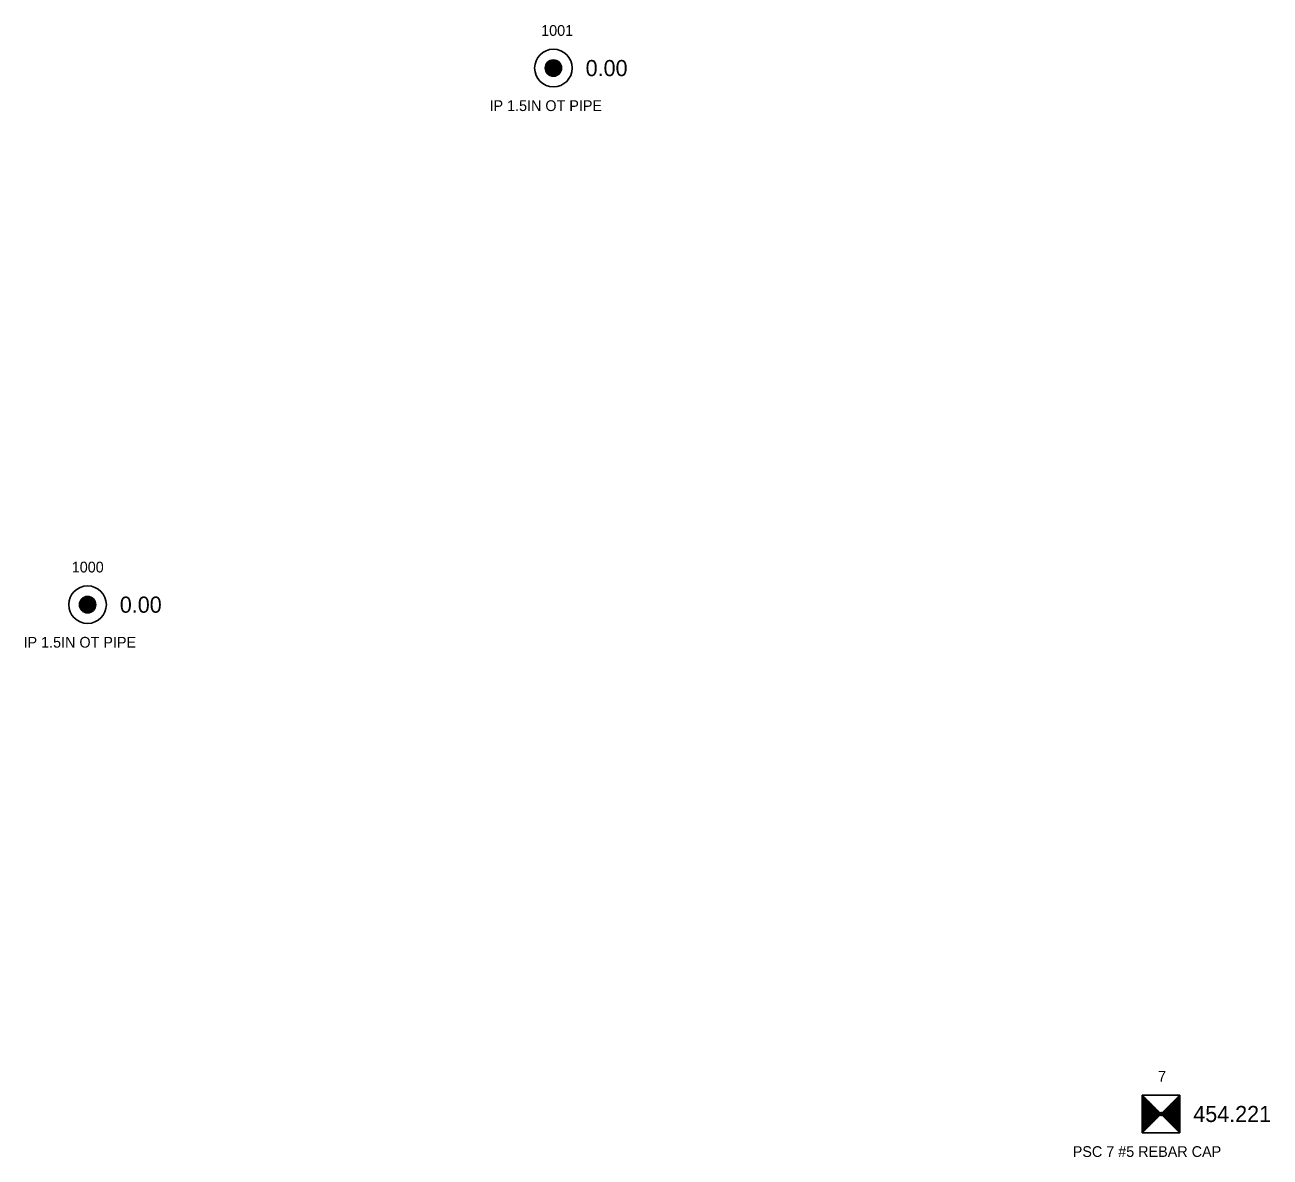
# Model space of a CAD drawing. Extents: x 1611865 to 1617004, y 775289 to 778546.
# Drawn here: x 1615669.9 to 1615785.8, y 776629.9 to 776735.3 of the extents above; entities that cross this region are included whole.
import ezdxf

# ---------------------------------------------------------------- set-up
doc = ezdxf.new("R2010")
doc.units = 0
for name, color, linetype in [('RD_EX_DV_Prop_txCode', 7, 'Continuous'), ('RD_EX_DV_PropPin', 7, 'Continuous'), ('RD_EX_TX_DV_Prop_ELEV', 7, 'Continuous'), ('RD_HC_Survey', 7, 'Continuous'), ('RD_HC_Survey_ELEV', 7, 'Continuous'), ('RD_HC_txCode', 7, 'Continuous'), ('RD_SMD_Locator', 7, 'Continuous')]:
    doc.layers.add(name, color=color, linetype=linetype)

msp = doc.modelspace()

# ---------------------------------------------------------------- linework, layer by layer
at = {"layer": 'RD_EX_DV_PropPin'}
for p, q in [((1615718.37, 776731.1), (1615718.37, 776731.49)), ((1615718.4, 776730.99), (1615718.4, 776731.59)), ((1615718.44, 776730.92), (1615718.44, 776731.66)), ((1615718.47, 776730.87), (1615718.47, 776731.72)), ((1615718.51, 776730.82), (1615718.51, 776731.77)), ((1615718.54, 776730.78), (1615718.54, 776731.81)), ((1615718.58, 776730.74), (1615718.58, 776731.84)), ((1615718.61, 776730.71), (1615718.61, 776731.87)), ((1615718.65, 776730.68), (1615718.65, 776731.9)), ((1615718.68, 776730.66), (1615718.68, 776731.93)), ((1615718.72, 776730.64), (1615718.72, 776731.95)), ((1615718.75, 776730.62), (1615718.75, 776731.97)), ((1615718.79, 776730.6), (1615718.79, 776731.99)), ((1615718.82, 776730.58), (1615718.82, 776732)), ((1615718.86, 776730.57), (1615718.86, 776732.01)), ((1615718.89, 776730.56), (1615718.89, 776732.02)), ((1615718.93, 776730.55), (1615718.93, 776732.03)), ((1615718.96, 776730.54), (1615718.96, 776732.04)), ((1615719, 776730.54), (1615719, 776732.05)), ((1615719.03, 776730.53), (1615719.03, 776732.05)), ((1615719.07, 776730.53), (1615719.07, 776732.05)), ((1615719.1, 776730.53), (1615719.1, 776732.05)), ((1615719.14, 776730.53), (1615719.14, 776732.05)), ((1615719.17, 776730.53), (1615719.17, 776732.05)), ((1615719.21, 776730.54), (1615719.21, 776732.05)), ((1615719.24, 776730.54), (1615719.24, 776732.04)), ((1615719.28, 776730.55), (1615719.28, 776732.03)), ((1615719.31, 776730.56), (1615719.31, 776732.02)), ((1615719.35, 776730.57), (1615719.35, 776732.01)), ((1615719.38, 776730.58), (1615719.38, 776732)), ((1615719.42, 776730.6), (1615719.42, 776731.99)), ((1615719.45, 776730.62), (1615719.45, 776731.97)), ((1615719.49, 776730.64), (1615719.49, 776731.95)), ((1615719.52, 776730.66), (1615719.52, 776731.93)), ((1615719.56, 776730.68), (1615719.56, 776731.9)), ((1615719.59, 776730.71), (1615719.59, 776731.87)), ((1615719.63, 776730.74), (1615719.63, 776731.84)), ((1615719.66, 776730.78), (1615719.66, 776731.81)), ((1615719.7, 776730.82), (1615719.7, 776731.77)), ((1615719.73, 776730.87), (1615719.73, 776731.72)), ((1615719.77, 776730.92), (1615719.77, 776731.66)), ((1615719.8, 776730.99), (1615719.8, 776731.59)), ((1615719.84, 776731.1), (1615719.84, 776731.49)), ((1615674.98, 776681.15), (1615674.98, 776681.54)), ((1615675.02, 776681.04), (1615675.02, 776681.64)), ((1615675.05, 776680.97), (1615675.05, 776681.71)), ((1615675.09, 776680.91), (1615675.09, 776681.77)), ((1615675.12, 776680.87), (1615675.12, 776681.82)), ((1615675.16, 776680.83), (1615675.16, 776681.86)), ((1615675.19, 776680.79), (1615675.19, 776681.89)), ((1615675.23, 776680.76), (1615675.23, 776681.92)), ((1615675.26, 776680.73), (1615675.26, 776681.95)), ((1615675.3, 776680.71), (1615675.3, 776681.98)), ((1615675.33, 776680.69), (1615675.33, 776682)), ((1615675.37, 776680.67), (1615675.37, 776682.02)), ((1615675.4, 776680.65), (1615675.4, 776682.03)), ((1615675.44, 776680.63), (1615675.44, 776682.05)), ((1615675.47, 776680.62), (1615675.47, 776682.06)), ((1615675.51, 776680.61), (1615675.51, 776682.07)), ((1615675.54, 776680.6), (1615675.54, 776682.08)), ((1615675.58, 776680.59), (1615675.58, 776682.09)), ((1615675.61, 776680.59), (1615675.61, 776682.1)), ((1615675.65, 776680.58), (1615675.65, 776682.1)), ((1615675.68, 776680.58), (1615675.68, 776682.1)), ((1615675.72, 776680.58), (1615675.72, 776682.1)), ((1615675.75, 776680.58), (1615675.75, 776682.1)), ((1615675.79, 776680.58), (1615675.79, 776682.1)), ((1615675.82, 776680.59), (1615675.82, 776682.1)), ((1615675.86, 776680.59), (1615675.86, 776682.09)), ((1615675.89, 776680.6), (1615675.89, 776682.08)), ((1615675.93, 776680.61), (1615675.93, 776682.07)), ((1615675.96, 776680.62), (1615675.96, 776682.06)), ((1615676, 776680.63), (1615676, 776682.05)), ((1615676.03, 776680.65), (1615676.03, 776682.03)), ((1615676.07, 776680.67), (1615676.07, 776682.02)), ((1615676.1, 776680.69), (1615676.1, 776682)), ((1615676.14, 776680.71), (1615676.14, 776681.98)), ((1615676.17, 776680.73), (1615676.17, 776681.95)), ((1615676.21, 776680.76), (1615676.21, 776681.92)), ((1615676.24, 776680.79), (1615676.24, 776681.89)), ((1615676.28, 776680.83), (1615676.28, 776681.86)), ((1615676.31, 776680.87), (1615676.31, 776681.82)), ((1615676.35, 776680.91), (1615676.35, 776681.77)), ((1615676.38, 776680.97), (1615676.38, 776681.71)), ((1615676.42, 776681.04), (1615676.42, 776681.64)), ((1615676.45, 776681.15), (1615676.45, 776681.54))]:
    msp.add_line(p, q, dxfattribs=at)
for centre, radius in [((1615719.1, 776731.29), 1.75), ((1615719.1, 776731.29), 0.761), ((1615675.72, 776681.34), 1.75), ((1615675.72, 776681.34), 0.761)]:
    msp.add_circle(centre, radius, dxfattribs=at)
at = {"layer": 'RD_HC_Survey'}
for p, q in [((1615773.93, 776635.68), (1615777.43, 776632.18)), ((1615777.43, 776635.68), (1615773.93, 776632.18)), ((1615773.96, 776635.66), (1615773.96, 776632.21)), ((1615773.98, 776635.63), (1615773.98, 776632.23)), ((1615774.01, 776635.61), (1615774.01, 776632.25)), ((1615774.03, 776635.58), (1615774.03, 776632.28)), ((1615774.06, 776635.56), (1615774.06, 776632.3)), ((1615774.08, 776635.53), (1615774.08, 776632.33)), ((1615774.11, 776635.51), (1615774.11, 776632.35)), ((1615774.13, 776635.48), (1615774.13, 776632.38)), ((1615774.16, 776635.46), (1615774.16, 776632.4)), ((1615774.18, 776635.43), (1615774.18, 776632.43)), ((1615774.21, 776635.41), (1615774.21, 776632.45)), ((1615774.23, 776635.38), (1615774.23, 776632.48)), ((1615774.26, 776635.36), (1615774.26, 776632.5)), ((1615774.28, 776635.33), (1615774.28, 776632.53)), ((1615774.31, 776635.31), (1615774.31, 776632.55)), ((1615774.33, 776635.28), (1615774.33, 776632.58)), ((1615774.35, 776635.26), (1615774.35, 776632.6)), ((1615774.38, 776635.23), (1615774.38, 776632.63)), ((1615774.4, 776635.21), (1615774.4, 776632.65)), ((1615774.43, 776635.19), (1615774.43, 776632.68)), ((1615774.45, 776635.16), (1615774.45, 776632.7)), ((1615774.48, 776635.14), (1615774.48, 776632.72)), ((1615774.5, 776635.11), (1615774.5, 776632.75)), ((1615774.53, 776635.09), (1615774.53, 776632.77)), ((1615774.55, 776635.06), (1615774.55, 776632.8)), ((1615774.58, 776635.04), (1615774.58, 776632.82)), ((1615774.6, 776635.01), (1615774.6, 776632.85)), ((1615774.63, 776634.99), (1615774.63, 776632.87)), ((1615774.65, 776634.96), (1615774.65, 776632.9)), ((1615774.68, 776634.94), (1615774.68, 776632.92)), ((1615774.7, 776634.91), (1615774.7, 776632.95)), ((1615774.73, 776634.89), (1615774.73, 776632.97)), ((1615774.75, 776634.86), (1615774.75, 776633)), ((1615774.78, 776634.84), (1615774.78, 776633.02)), ((1615774.8, 776634.81), (1615774.8, 776633.05)), ((1615774.83, 776634.79), (1615774.83, 776633.07)), ((1615774.85, 776634.76), (1615774.85, 776633.1)), ((1615774.87, 776634.74), (1615774.87, 776633.12)), ((1615774.9, 776634.72), (1615774.9, 776633.15)), ((1615774.92, 776634.69), (1615774.92, 776633.17)), ((1615776.44, 776634.69), (1615776.44, 776633.17)), ((1615776.47, 776634.72), (1615776.47, 776633.15)), ((1615776.49, 776634.74), (1615776.49, 776633.12)), ((1615776.52, 776634.76), (1615776.52, 776633.1)), ((1615776.54, 776634.79), (1615776.54, 776633.07)), ((1615776.57, 776634.81), (1615776.57, 776633.05)), ((1615776.59, 776634.84), (1615776.59, 776633.02)), ((1615776.62, 776634.86), (1615776.62, 776633)), ((1615776.64, 776634.89), (1615776.64, 776632.97)), ((1615776.67, 776634.91), (1615776.67, 776632.95)), ((1615776.69, 776634.94), (1615776.69, 776632.92)), ((1615776.72, 776634.96), (1615776.72, 776632.9)), ((1615776.74, 776634.99), (1615776.74, 776632.87)), ((1615776.77, 776635.01), (1615776.77, 776632.85)), ((1615776.79, 776635.04), (1615776.79, 776632.82)), ((1615776.82, 776635.06), (1615776.82, 776632.8)), ((1615776.84, 776635.09), (1615776.84, 776632.77)), ((1615776.86, 776635.11), (1615776.86, 776632.75)), ((1615776.89, 776635.14), (1615776.89, 776632.72)), ((1615776.91, 776635.16), (1615776.91, 776632.7)), ((1615776.94, 776635.19), (1615776.94, 776632.68)), ((1615776.96, 776635.21), (1615776.96, 776632.65)), ((1615776.99, 776635.23), (1615776.99, 776632.63)), ((1615777.01, 776635.26), (1615777.01, 776632.6)), ((1615777.04, 776635.28), (1615777.04, 776632.58)), ((1615777.06, 776635.31), (1615777.06, 776632.55)), ((1615777.09, 776635.33), (1615777.09, 776632.53)), ((1615777.11, 776635.36), (1615777.11, 776632.5)), ((1615777.14, 776635.38), (1615777.14, 776632.48)), ((1615777.16, 776635.41), (1615777.16, 776632.45)), ((1615777.19, 776635.43), (1615777.19, 776632.43)), ((1615777.21, 776635.46), (1615777.21, 776632.4)), ((1615777.24, 776635.48), (1615777.24, 776632.38)), ((1615777.26, 776635.51), (1615777.26, 776632.35)), ((1615777.29, 776635.53), (1615777.29, 776632.33)), ((1615777.31, 776635.56), (1615777.31, 776632.3)), ((1615777.34, 776635.58), (1615777.34, 776632.28)), ((1615777.36, 776635.61), (1615777.36, 776632.25)), ((1615777.38, 776635.63), (1615777.38, 776632.23)), ((1615777.41, 776635.66), (1615777.41, 776632.21)), ((1615774.95, 776634.67), (1615774.95, 776633.2)), ((1615774.97, 776634.64), (1615774.97, 776633.22)), ((1615775, 776634.62), (1615775, 776633.24)), ((1615775.02, 776634.59), (1615775.02, 776633.27)), ((1615775.05, 776634.57), (1615775.05, 776633.29)), ((1615775.07, 776634.54), (1615775.07, 776633.32)), ((1615775.1, 776634.52), (1615775.1, 776633.34)), ((1615775.12, 776634.49), (1615775.12, 776633.37)), ((1615775.15, 776634.47), (1615775.15, 776633.39)), ((1615775.17, 776634.44), (1615775.17, 776633.42)), ((1615775.2, 776634.42), (1615775.2, 776633.44)), ((1615775.22, 776634.39), (1615775.22, 776633.47)), ((1615775.25, 776634.37), (1615775.25, 776633.49)), ((1615775.27, 776634.34), (1615775.27, 776633.52)), ((1615775.3, 776634.32), (1615775.3, 776633.54)), ((1615775.32, 776634.29), (1615775.32, 776633.57)), ((1615775.34, 776634.27), (1615775.34, 776633.59)), ((1615775.37, 776634.24), (1615775.37, 776633.62)), ((1615775.39, 776634.22), (1615775.39, 776633.64)), ((1615775.42, 776634.2), (1615775.42, 776633.67)), ((1615775.44, 776634.17), (1615775.44, 776633.69)), ((1615775.47, 776634.15), (1615775.47, 776633.71)), ((1615775.49, 776634.12), (1615775.49, 776633.74)), ((1615775.52, 776634.1), (1615775.52, 776633.76)), ((1615775.54, 776634.07), (1615775.54, 776633.79)), ((1615775.57, 776634.05), (1615775.57, 776633.81)), ((1615775.59, 776634.02), (1615775.59, 776633.84)), ((1615775.62, 776634), (1615775.62, 776633.86)), ((1615775.64, 776633.97), (1615775.64, 776633.89)), ((1615775.67, 776633.95), (1615775.67, 776633.91)), ((1615775.7, 776633.95), (1615775.7, 776633.91)), ((1615775.73, 776633.97), (1615775.73, 776633.89)), ((1615775.75, 776634), (1615775.75, 776633.86)), ((1615775.78, 776634.02), (1615775.78, 776633.84)), ((1615775.8, 776634.05), (1615775.8, 776633.81)), ((1615775.83, 776634.07), (1615775.83, 776633.79)), ((1615775.85, 776634.1), (1615775.85, 776633.76)), ((1615775.87, 776634.12), (1615775.87, 776633.74)), ((1615775.9, 776634.15), (1615775.9, 776633.71)), ((1615775.92, 776634.17), (1615775.92, 776633.69)), ((1615775.95, 776634.2), (1615775.95, 776633.67)), ((1615775.97, 776634.22), (1615775.97, 776633.64)), ((1615776, 776634.24), (1615776, 776633.62)), ((1615776.02, 776634.27), (1615776.02, 776633.59)), ((1615776.05, 776634.29), (1615776.05, 776633.57)), ((1615776.07, 776634.32), (1615776.07, 776633.54)), ((1615776.1, 776634.34), (1615776.1, 776633.52)), ((1615776.12, 776634.37), (1615776.12, 776633.49)), ((1615776.15, 776634.39), (1615776.15, 776633.47)), ((1615776.17, 776634.42), (1615776.17, 776633.44)), ((1615776.2, 776634.44), (1615776.2, 776633.42)), ((1615776.22, 776634.47), (1615776.22, 776633.39)), ((1615776.25, 776634.49), (1615776.25, 776633.37)), ((1615776.27, 776634.52), (1615776.27, 776633.34)), ((1615776.3, 776634.54), (1615776.3, 776633.32)), ((1615776.32, 776634.57), (1615776.32, 776633.29)), ((1615776.35, 776634.59), (1615776.35, 776633.27)), ((1615776.37, 776634.62), (1615776.37, 776633.24)), ((1615776.39, 776634.64), (1615776.39, 776633.22)), ((1615776.42, 776634.67), (1615776.42, 776633.2))]:
    msp.add_line(p, q, dxfattribs=at)
msp.add_lwpolyline([(1615777.43, 776635.68), (1615773.93, 776635.68), (1615773.93, 776632.18), (1615777.43, 776632.18)], close=True, dxfattribs=at)
at = {"layer": 'RD_SMD_Locator'}
for centre in [(1615719.1, 776731.29), (1615675.72, 776681.34), (1615775.68, 776633.93)]:
    msp.add_circle(centre, 0.15, dxfattribs=at)

# ---------------------------------------------------------------- texts
at = {"layer": 'RD_EX_DV_Prop_txCode'}
for s, p in [('1001', (1615717.96, 776734.29)), ('IP 1.5IN OT PIPE', (1615713.15, 776727.29)), ('1000', (1615674.25, 776684.34)), ('IP 1.5IN OT PIPE', (1615669.76, 776677.34))]:
    msp.add_text(s, height=1, dxfattribs=at).set_placement(p)
at = {"layer": 'RD_EX_TX_DV_Prop_ELEV'}
for p in [(1615722.1, 776730.54), (1615678.72, 776680.59)]:
    msp.add_text('0.00', height=1.5, dxfattribs=at).set_placement(p)
at = {"layer": 'RD_HC_Survey_ELEV'}
msp.add_text('454.221', height=1.5, dxfattribs=at).set_placement((1615778.68, 776633.18))
at = {"layer": 'RD_HC_txCode'}
for s, p in [('7', (1615775.4, 776636.93)), ('PSC 7 #5 REBAR CAP', (1615767.46, 776629.93))]:
    msp.add_text(s, height=1, dxfattribs=at).set_placement(p)

doc.saveas('drawing.dxf')
